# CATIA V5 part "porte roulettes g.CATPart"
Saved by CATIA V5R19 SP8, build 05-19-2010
Part number: porte roulettes g
Publications: "profondeur_lamage"
Bounding box of the stored display mesh (mm): x -12.5 to 0, y -14.496 to 16, z -10 to 5
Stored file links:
  G:\EU_thinkMotion\CFAO_2010\MMS_groupe3\MMS_groupe3\A reprendre\ftixier\florent-tixier\florent-tixier\porte roulettes g.CATPart
  G:\EU_thinkMotion\CFAO_2010\MMS_groupe3\MMS_groupe3\A reprendre\ftixier\florent-tixier\florent-tixier\porte roulette.CATPart
  C:\Users\Azote\Desktop\CFAO\coupe_tube1.CATProduct
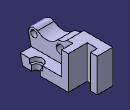
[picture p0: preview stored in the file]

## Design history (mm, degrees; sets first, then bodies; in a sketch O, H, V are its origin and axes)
Parameters
  LENGTH = 5 mm
  LENGTH = 12 mm
  profondeur_lamage = 2 mm
External parameters (linked from other documents)
  External.R11 = 5 mm
  External.rayon_axe_rouleau = 2 mm
  `External.rayon_axe_roulette coupe` = 1.5 mm
  External.diametre_gorge_vis = 4 mm
  External.diametre_tete_vis = 5 mm
Set1
  Point1 "centre_roulette_coupe": linked copy from another document
  Point2 "centre_rouleau": linked copy from another document
  Line1 "Axe_vis": linked copy from another document
Body1 (main body)
  Sketch1 on yz-plane, origin (0, 0, 0), H (0, 1, 0), V (0, 0, 1)
    line L1 (16, -10) -> (-12, -10)
    line L2 (-12, -10) -> (-14.4959, -0.1425)
    point P3 (-14.4959, -0.1425)
    point P4 (-14.4959, -0.1425)
    arc A1 centre (-12, 0) radius 2.5 from (-14.4959, -0.1425) to (-10.3925, 1.9147) cw
    line L3 (16, -10) -> (16, 5)
    line L4 (16, 5) -> (3, 5)
    reference projected point E1 (-12, 0)
    arc A2 centre (-6.3469, 6.7333) radius 6.2917 from (-10.3925, 1.9147) to (-1.2388, 3.06) ccw
    arc A3 centre (-0.7939, 7.6887) radius 4.6501 from (-1.2388, 3.06) to (3, 5) ccw
    point P11 (-1.2388, 3.06)
    reference projected line E2 (-6, -42.6969) -> (-6, 52.3031)
    reference projected line E3 (14, 0) -> (-26, 0)
    reference projected line E4 (14, 0) -> (-26, 0)
    circle A4 centre (0, 0) radius 2
    circle A5 centre (-12, 0) radius 1.5
    reference projected point E5 (0, 0) from Point2
    reference projected point E6 (-12, 0) from Point1
    length L1 = 28 {= LENGTH +16mm}
    radius A1 = 2.5
    length L4 = 13
    distance L3 E2 = 22
    distance E3 L4 = 5 {= LENGTH}
    distance L1 E4 = 10
    radius A5 = 1.5 {= `External.rayon_axe_roulette coupe`}
    radius A4 = 2 {= External.rayon_axe_rouleau}
    horizontal: L1 H, L4 H
    vertical: L3 V
    concentricity: E1 A1, A4 E5, A5 E6
    coincidence: P4 P3, A3 P11, P11 A2
    tangency: A2 A1
  Pad1: profile Sketch1, direction (-1, 0, 0), length 12.5
  Sketch2 on xy-plane, origin (0, 0, 0), H (1, 0, 0), V (0, 1, 0)
    point P1 (0, 5.5)
    line L1 (0, 5.5) -> (-5, 5.5)
    line L2 (-5, 5.5) -> (-5, -17.4603)
    line L3 (-5, -17.4603) -> (0, -17.4603)
    line L4 (0, -17.4603) -> (0, 5.5)
    reference projected line E1 (0, 16) -> (-4, 16) from edge [face of Pad1 from Sketch1.L3 | face of Pad1 from Sketch1.L4]
    length L1 = 5
    distance L1 E1 = 10.5
    coincidence: P1 V
    horizontal: L1 H, L3 H
    vertical: L2 V, L4 V
  Pocket1: profile Sketch2, direction (0, 0, -1), length 5.5 {= External.R11+0.5mm}, opposite side length 5 {= External.R11}
  Sketch3 on end face of Pocket1, origin (-1.6073, -7.6892, -5.5), H (1, 0, 0), V (0, 1, 0)
    point P1 (1.6073, 1.6892)
    reference projected point E1 (1.6073, 1.6892) from Line1
    coincidence: P1 E1
  Hole1: placed by Sketch3, at (0, -6, -5.5) direction (0, 0, -1), diameter 4 {= External.diametre_gorge_vis}, through (limit type 6), counterbore diameter 6 {= External.diametre_tete_vis +1mm}, counterbore depth 2 {= profondeur_lamage}
  Sketch4 on face of Pad1 from Sketch1.L4, origin (0, 0, 5), H (1, 0, 0), V (0, 1, 0)
    line L1 (-5.5, 16) -> (-5.5, 13)
    line L2 (-5.5, 13) -> (-8.5, 13)
    line L3 (-8.5, 13) -> (-8.5, 8.5)
    line L4 (-8.5, 8.5) -> (0, 8.5)
    point P5 (0, 8.5)
    line L5 (0, 8.5) -> (0, 16)
    line L6 (0, 16) -> (-5.5, 16)
    reference projected line E1 (0, 16) -> (-7, 16) from edge [face of Pad1 from Sketch1.L3 | face of Pad1 from Sketch1.L4]
    length L3 = 4.5
    length L1 = 3
    distance L5 L3 = 8.5
    distance L1 L3 = 3
    vertical: L1 V, L3 V, L5 V
    horizontal: L2 H, L4 H, L6 H
    coincidence: P5 V, L6 E1
  Pocket2: profile Sketch4, direction (0, 0, -1), through (limit type 6)
Relations
  Hole1.Depth = `détruit_prodondeur_trou` (deactivated)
